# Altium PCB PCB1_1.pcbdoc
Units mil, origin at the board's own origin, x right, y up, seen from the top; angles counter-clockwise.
Board outline 3218.62 x 3136.34 mil, 4 copper layers (Top Layer, GND, VIN, Bottom Layer), stack 64.007 mil thick; 37 components, 44 nets, 178 pads, 47 vias.
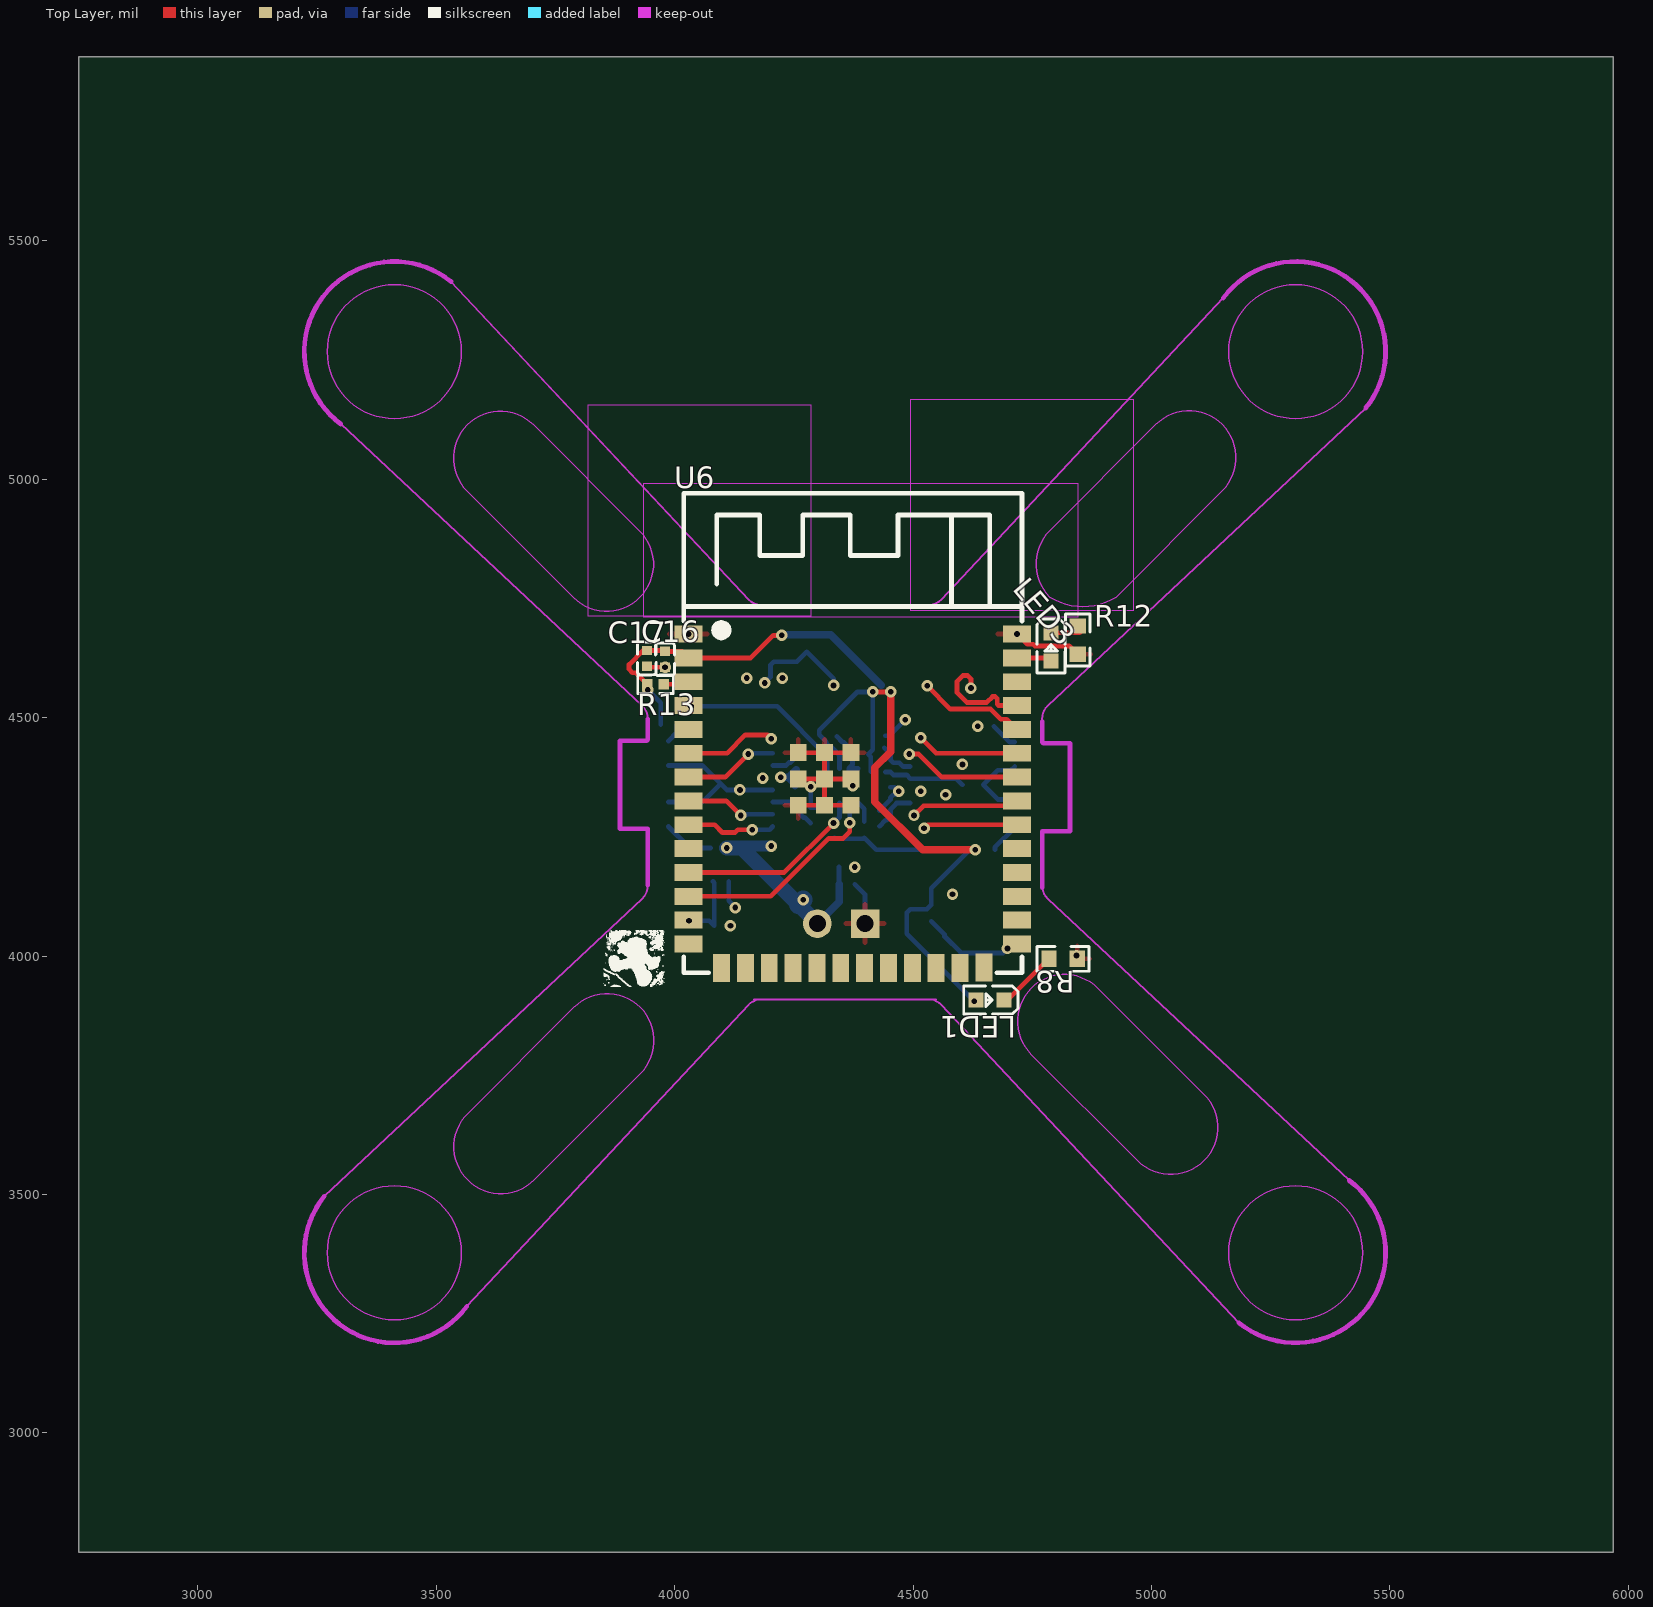
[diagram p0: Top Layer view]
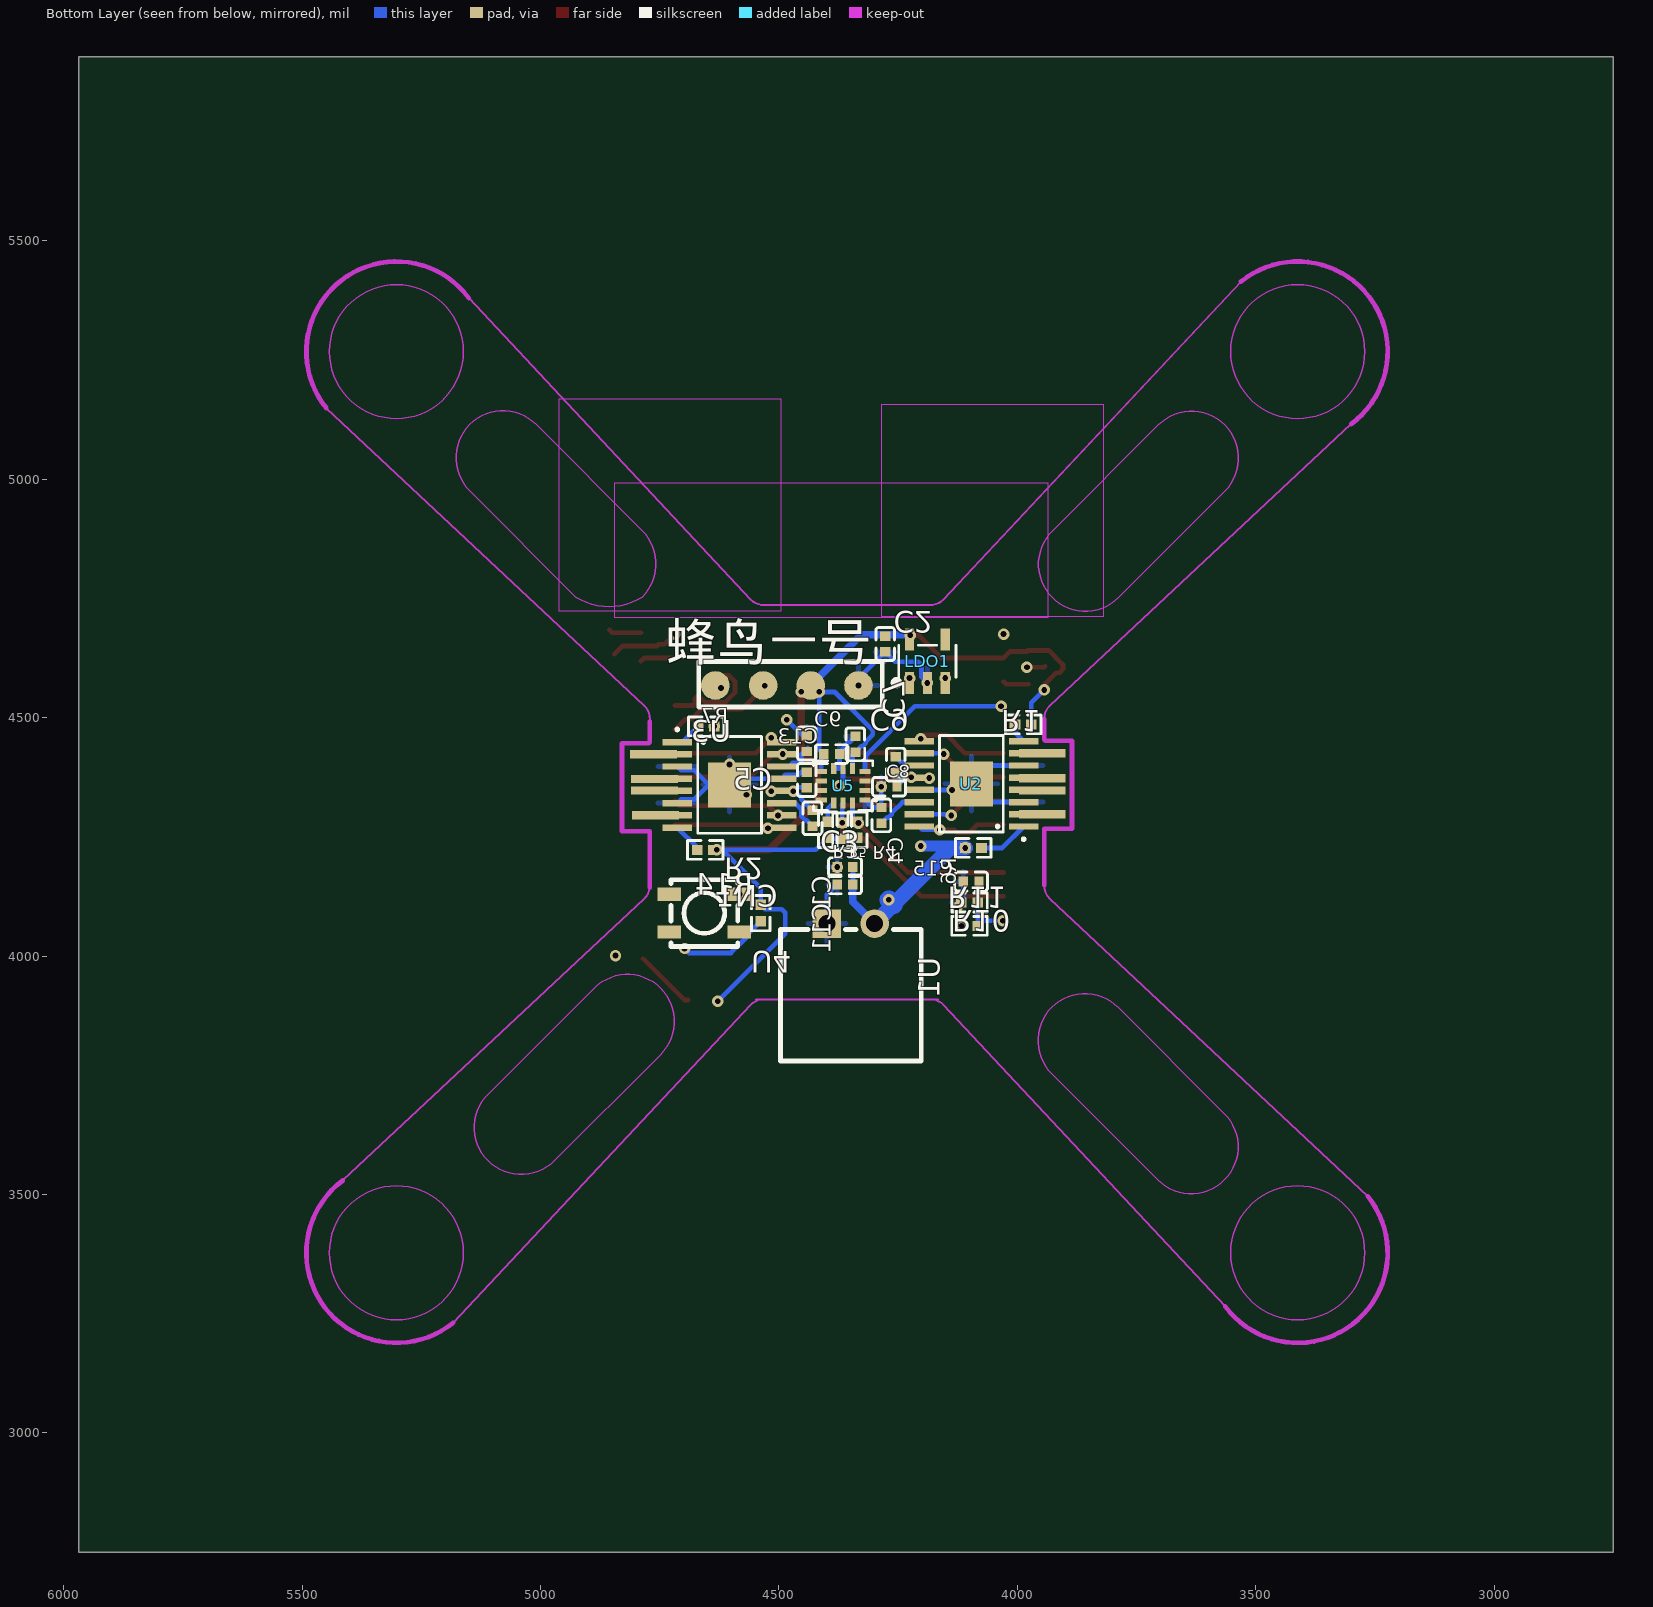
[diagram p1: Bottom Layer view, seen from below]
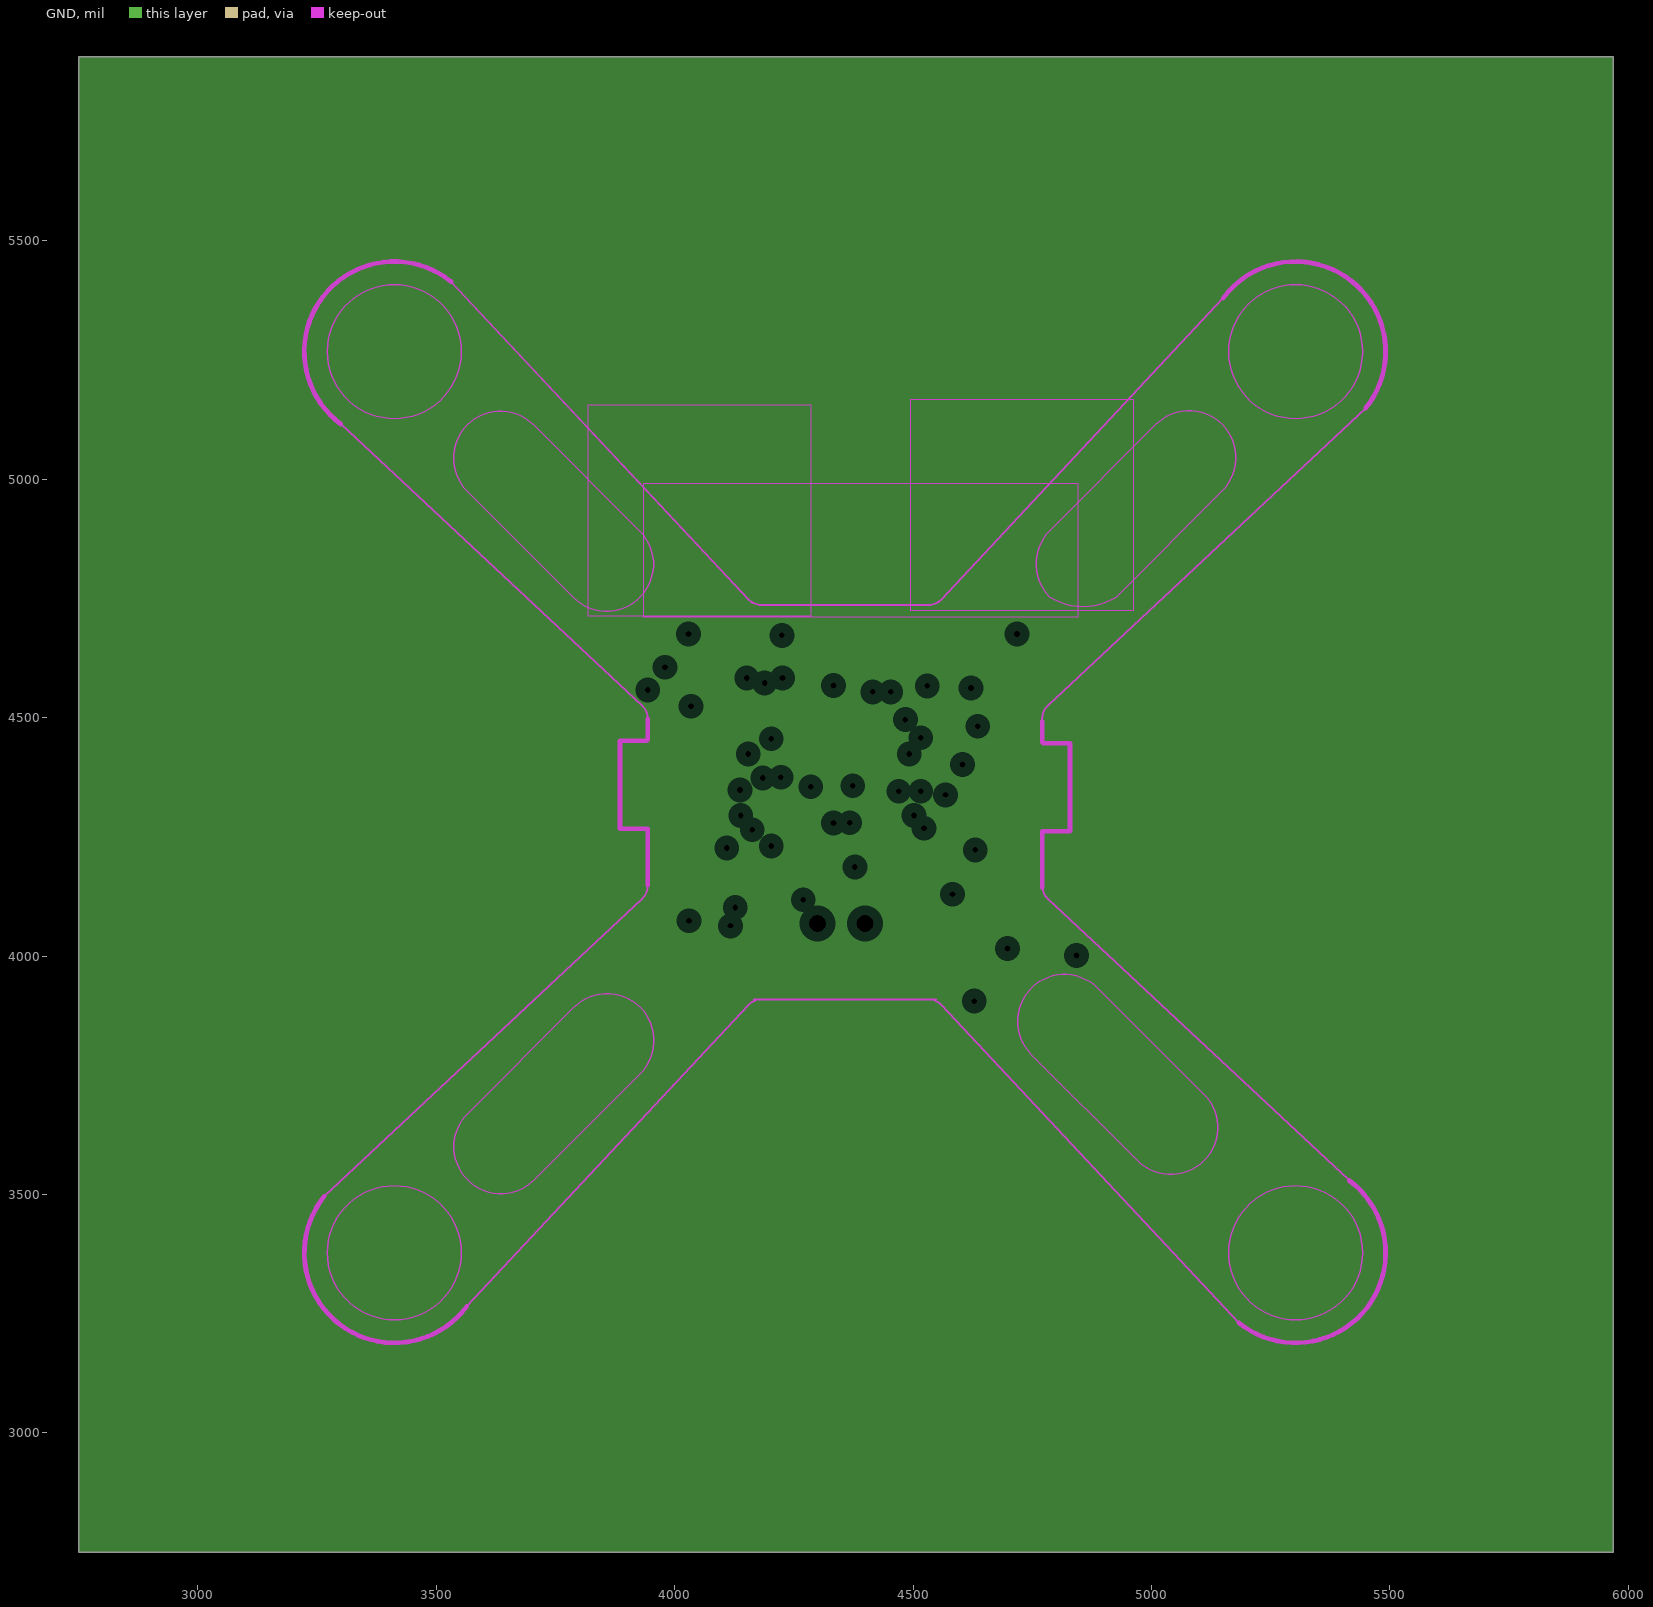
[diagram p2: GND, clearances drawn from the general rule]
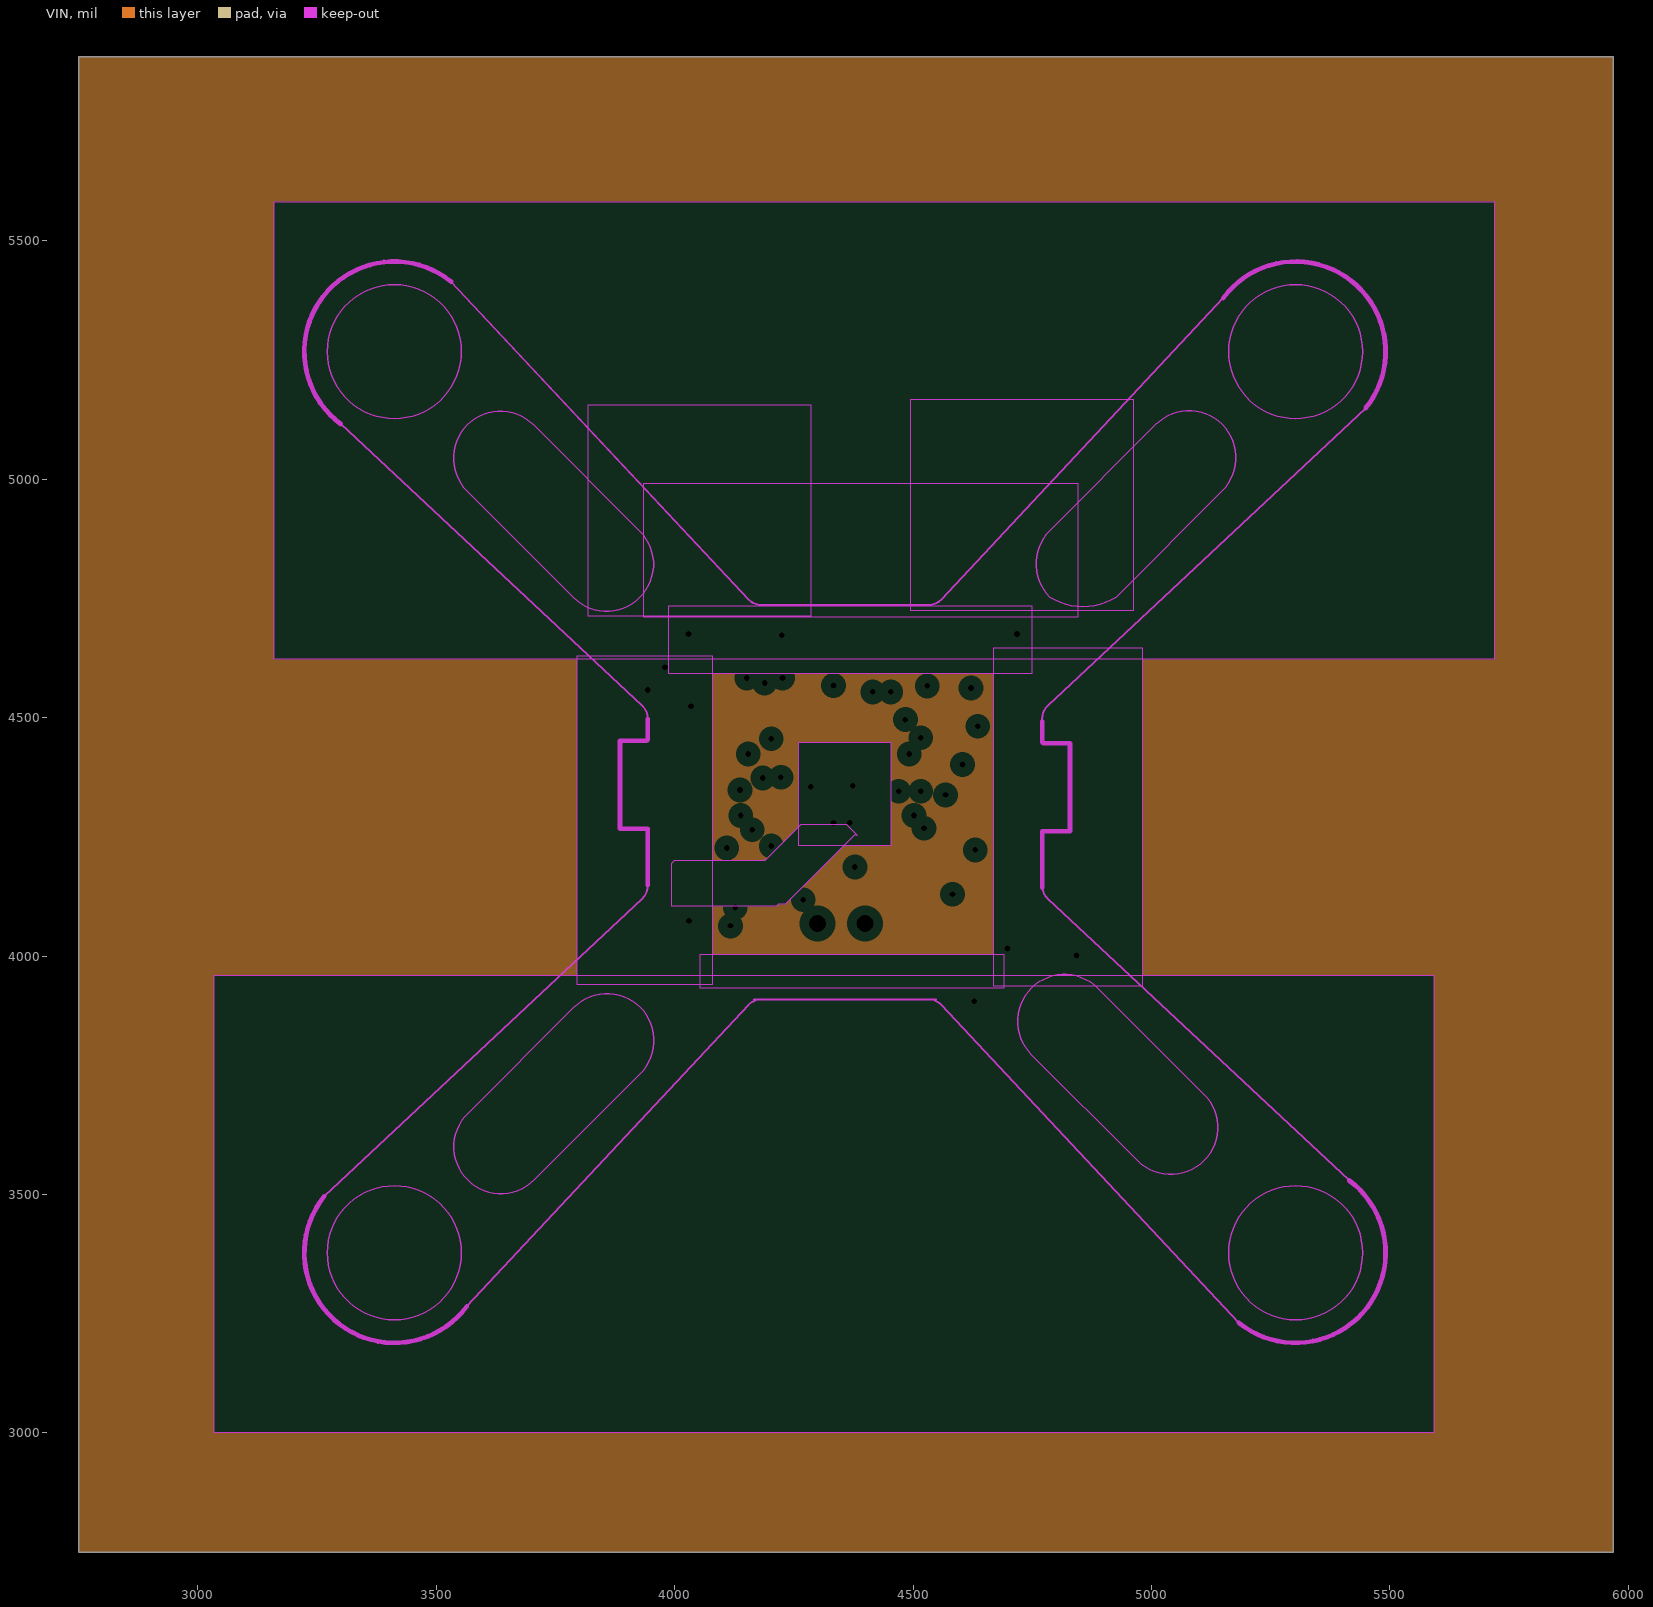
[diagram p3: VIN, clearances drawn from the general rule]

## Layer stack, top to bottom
Top Layer: signal copper 1.378
Dielectric1: surface 8.283, 7628 RC49% 8.6mil, Dk 0
GND: plane copper 1.378
Dielectric2: surface 41.929, 1.1mm H/HOZ Copper, Dk 0
VIN: plane copper 1.378
Dielectric3: surface 8.283, 7628 RC49% 8.6mil, Dk 0
Bottom Layer: signal copper 1.378

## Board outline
5968.62,2750 2750,2750 2750,5886.34 5968.62,5886.34

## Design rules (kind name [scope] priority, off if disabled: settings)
BoardOutlineClearance copperThickness1oz [All] p0: genericclearance=10 ignorepadtopadclearanceinfootprint=FALSE except(0: Arc-SplitContinuation Track-SplitContinuation SMDPad-SplitContinuation THPad-SplitContinuation Via-SplitContinuation Fill-SplitContinuation Poly-SplitContinuation Region-SplitContinuation Text-SplitContinuation)
BoardOutlineClearance copperThickness2oz [All] p0: genericclearance=10 ignorepadtopadclearanceinfootprint=FALSE except(0: Arc-SplitContinuation Track-SplitContinuation SMDPad-SplitContinuation THPad-SplitContinuation Via-SplitContinuation Fill-SplitContinuation Poly-SplitContinuation Region-SplitContinuation Text-SplitContinuation)
BoardOutlineClearance copperThicknessInner0.5oz [All] p0: genericclearance=10 ignorepadtopadclearanceinfootprint=FALSE except(0: Arc-SplitContinuation Track-SplitContinuation SMDPad-SplitContinuation THPad-SplitContinuation Via-SplitContinuation Fill-SplitContinuation Poly-SplitContinuation Region-SplitContinuation Text-SplitContinuation)
BoardOutlineClearance otherClearance [All] p0: genericclearance=10 ignorepadtopadclearanceinfootprint=FALSE except(0: Arc-SplitContinuation Track-SplitContinuation SMDPad-SplitContinuation THPad-SplitContinuation Via-SplitContinuation Fill-SplitContinuation Poly-SplitContinuation Region-SplitContinuation Text-SplitContinuation)
Clearance copperThickness1oz [All] p1: gap=7 ignorepadtopadclearanceinfootprint=FALSE
Clearance copperThickness2oz [All] p1: gap=7 ignorepadtopadclearanceinfootprint=FALSE
Clearance copperThicknessInner0.5oz [All] p1: gap=7 ignorepadtopadclearanceinfootprint=FALSE
Clearance otherClearance [All] p1: gap=7 ignorepadtopadclearanceinfootprint=FALSE
DiffPairsRouting differentialPair [All] p1: maxuncoupledlength=10 minlimit=5.9843 maxlimit=Infinity mostfreqgap=5.9843 toplayer_minwidth=5 toplayer_prefwidth=10 toplayer_maxwidth=100 bottomlayer_minwidth=5 bottomlayer_prefwidth=10 bottomlayer_maxwidth=100
PasteMaskExpansion pasteMaskExpansion [All] p1: expansion=0
PlaneConnect innerPlane [All] p1: planeconnectstyle=Relief reliefexpansion=20 reliefentries=4 reliefconductorwidth=10 reliefairgap=10
PolygonConnect copperRegion [All] p1: connectstyle=Relief reliefentries=4 reliefconductorwidth=10 polygonreliefangle="90 Angle" airgapwidth=10
RoutingVias viaSize [All] p1: viastyle="Through Hole" holewidth=12.0078 minholewidth=7.874 maxholewidth=248.0314 width=12.0078 minwidth=7.874 maxwidth=248.0314
SolderMaskExpansion solderMaskExpansion [All] p1: useseparateexpansions=TRUE expansion=2.0079 expansionbottom=2.0079
Width copperThickness1oz [All] p1: maxlimit=100 minlimit=4 preferedwidth=10
Width copperThickness2oz [All] p1: maxlimit=100 minlimit=8 preferedwidth=10
Width copperThickness0.5oz [All] p1: maxlimit=100 minlimit=4 preferedwidth=10

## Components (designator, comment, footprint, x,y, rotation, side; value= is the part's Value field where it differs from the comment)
C1 "" C0402 4361.34,4186.65 r180 bottom
C2 "" C0402 4277.01,4654.49 r270 bottom
C3 "" C0402 4429.61,4289.06 r90 bottom
C4 "" C0402 4285.04,4295.08 r90 bottom
C5 "" C0402 4441.65,4369.37 r270 bottom
C6 "" C0402 4441.65,4445.67 r90 bottom
C7 "" C0402 4254.92,4401.5 r270 bottom
C8 "" C0402 4268.98,4355.31 r0 bottom
C9 "" C0402 4339.73,4444.14 r90 bottom
C11 "" C0402 4361.34,4150.51 r180 bottom
C13 "" C0402 4389.45,4423.58 r180 bottom
C15 "" C0402 4097.02,4156.53 r180 bottom
C16 "" C0402 3979.84,4622.36 r90 top
C17 "" C0402 3941.69,4624.37 r90 top
CN1 "" CONN-TH_2P-P2.50_WAFER-XH254WZ-2A 4349.29,4068.19 r180 bottom
LDO1 "" SOT-23-5_L3.0-W1.7-P0.95-LS2.8-BL 4188.66,4618.35 r180 bottom
LED1 "" LED0603-RD 4661.15,3908.18 r180 top
LED3 "" LED0603-RD 4789.02,4648.46 r270 top
R1 "" R0402 3987.87,4485.83 r0 bottom
R2 "" R0402 4654.49,4222.8 r0 bottom
R3 "" R0402 4397.48,4264.96 r270 bottom
R4 "" R0402 4335.24,4264.96 r270 bottom
R5 "" R0402 4367.36,4262.95 r270 bottom
R6 "" R0402 4092.28,4226.81 r180 bottom
R7 "" R0402 4652.48,4481.81 r0 bottom
R8 "" R0603 4814.48,3994.36 r0 top
R10 "" R0402 4100.3,4063.44 r0 bottom
R11 "" R0402 4100.31,4112.36 r180 bottom
R12 "" R0603 4845.24,4662.52 r270 top
R13 "" R0402 3959.76,4570.16 r0 top
R14 "" R0402 4538.03,4090.28 r270 bottom
U1 "" 4p贴片 4043.15,4207.56 r90 bottom
U2 "" ETSSOP-16_L5.0-W4.4-P0.65-LS6.4-BL-EP 4096.3,4361.34 r90 bottom
U3 "" ETSSOP-16_L5.0-W4.4-P0.65-LS6.4-BL-EP 4603.54,4359.18 r270 bottom
U4 "" KEY-SMD_4P-L3.3-W3.3-P2.00-LS4.0 4656.5,4090.28 r0 bottom
U5 "" LGA-14_L3.0-W2.5-P0.50-BR 4365.35,4357.32 r180 bottom
U6 "" WIRELM-SMD_ESP32-S3-WROOM-1 4373.39,4325.2 r0 top

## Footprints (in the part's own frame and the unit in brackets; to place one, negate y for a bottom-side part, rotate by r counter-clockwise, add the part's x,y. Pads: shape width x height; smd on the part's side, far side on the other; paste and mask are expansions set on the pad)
4p贴片 [mil]
  round 60 smd: 1(360,590) 2(360,490) 3(360,390) 4(360,290)
  silkscreen extent 315,240 410,625
C0402 [mm]
  rect 0.5x0.54 smd: 1(-0.42,0) 2(0.42,0)
  silkscreen extent -0.87,-0.5 0.87,0.5
CONN-TH_2P-P2.50_WAFER-XH254WZ-2A [mil]
  rect 60x60 hole 36: 1(-50.01,0)
  round 60 hole 36: 2(49.99,0)
  silkscreen extent -148,-288 148,-13
ETSSOP-16_L5.0-W4.4-P0.65-LS6.4-BL-EP [mm]
  rect 0.343x1.56 smd: 1(-2.275,-2.78) 2(-1.625,-2.78) 3(-0.975,-2.78) 4(-0.325,-2.78) 5(0.325,-2.78) 6(0.975,-2.78) 7(1.625,-2.78) 8(2.275,-2.78) 9(2.275,2.78) 10(1.625,2.78) 11(0.975,2.78) 12(0.325,2.78) 13(-0.325,2.78) 14(-0.975,2.78) 15(-1.625,2.78) 16(-2.275,2.78)
  rect 2.4x2.3 smd: 17(0,0)
  silkscreen extent -3.02,-2.85 2.58,1.7
KEY-SMD_4P-L3.3-W3.3-P2.00-LS4.0 [mm]
  rect 1.25x0.7 smd: 1(-1.875,1) 2(1.875,1) 3(-1.875,-1) 4(1.875,-1)
  silkscreen extent -1.78,-1.78 1.78,1.78
LED0603-RD [mm]
  rect 0.8x0.8 smd: 1(-0.749,0) 2(0.749,0)
  silkscreen extent -1.49,-0.75 1.39,0.76
LGA-14_L3.0-W2.5-P0.50-BR [mm]
  rect 0.6x0.27 smd: 1(1.17,-0.75) 2(1.17,-0.25) 3(1.17,0.25) 4(1.17,0.75) 8(-1.17,0.75) 9(-1.17,0.25) 10(-1.17,-0.25) 11(-1.17,-0.75)
  rect 0.27x0.6 smd: 5(0.5,0.92) 6(0,0.92) 7(-0.5,0.92) 12(-0.5,-0.92) 13(0,-0.92) 14(0.5,-0.92)
  silkscreen extent -1.58,-1.33 1.8,1.33
R0402 [mm]
  rect 0.566x0.54 smd: 1(-0.433,0) 2(0.433,0)
  silkscreen extent -0.94,-0.5 0.94,0.5
R0603 [mil]
  rect 31.75x34.02 smd: 1(-29.66,0) 2(29.66,0)
  silkscreen extent -55,-26 55,26
SOT-23-5_L3.0-W1.7-P0.95-LS2.8-BL [mm]
  rect 0.49x1.157 smd: 1(-0.95,-1.154) 2(0,-1.154) 3(0.95,-1.154)
  rect 0.49x1.175 smd: 4(0.95,1.154) 5(-0.95,1.154)
  silkscreen extent -1.8,-1.29 1.53,0.85
WIRELM-SMD_ESP32-S3-WROOM-1 [mm]
  rect 1.5x0.9 smd: 1(-8.75,8.895) 2(-8.75,7.625) 3(-8.75,6.355) 4(-8.75,5.085) 5(-8.75,3.815) 6(-8.75,2.545) 7(-8.75,1.275) 8(-8.75,0.005) 9(-8.75,-1.265) 10(-8.75,-2.535) 11(-8.75,-3.805) 12(-8.75,-5.075) 13(-8.75,-6.345) 14(-8.75,-7.615) 27(8.75,-7.615) 28(8.75,-6.345) 29(8.75,-5.075) 30(8.75,-3.805) 31(8.75,-2.535) 32(8.75,-1.265) 33(8.75,0.005) 34(8.75,1.275) 35(8.75,2.545) 36(8.75,3.815) 37(8.75,5.085) 38(8.75,6.355) 39(8.75,7.625) 40(8.75,8.895)
  rect 0.9x1.5 smd: 15(-6.985,-8.895) 16(-5.715,-8.895) 17(-4.445,-8.895) 18(-3.175,-8.895) 19(-1.905,-8.895) 20(-0.635,-8.895) 21(0.635,-8.895) 22(1.905,-8.895) 23(3.175,-8.895) 24(4.445,-8.895) 25(5.715,-8.895) 26(6.985,-8.865)
  rect 0.9x0.9 smd: 41(-2.9,-0.225) 41(-2.9,1.175) 41(-2.9,2.575) 41(-1.5,-0.225) 41(-1.5,1.175) 41(-1.5,2.575) 41(-0.1,-0.225) 41(-0.1,1.175) 41(-0.1,2.575)
  silkscreen extent -9,-9.14 9.02,16.39

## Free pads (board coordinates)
  rect 98.43x17.72 smd far side: 1(3947.72,4297.09) 1(3947.72,4347.28) 1(3947.72,4373.39) 1(3947.72,4425.59) 1(4758.9,4295.08) 1(4760.91,4347.28) 1(4760.91,4371.38) 1(4762.91,4423.58)

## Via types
v1: diameter 24.02, hole 12.01, Top Layer to Bottom Layer, 47 vias

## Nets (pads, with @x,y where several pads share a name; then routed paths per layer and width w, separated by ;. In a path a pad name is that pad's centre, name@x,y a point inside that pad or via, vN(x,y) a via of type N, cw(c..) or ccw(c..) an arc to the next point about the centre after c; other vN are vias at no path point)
3.3V: C2.1 C9.1 C13.1 C16.2 C17.2 LDO1.5 LED1.2 R1.1 R2.1 R3.2 R4.2 R5.2 R13.1 R14.1 U1.3 U5.5 U5.8 U6.2 | length 2453.9
  Top Layer w10: R13.1 3918.63,4594.25 3911.57,4594.25 3904.5,4601.32 3904.5,4611.32 3934.09,4640.91 C17.2 3977.83,4640.91 C16.2 4015.39,4638.9 U6.2 4159.56,4625.39 4206.73,4672.56 v1(4224.8,4672.56) ; v1(4415.55,4554.09) v1(4453.05,4554.09)
  Top Layer w15.75: v1(4453.05,4554.09) 4453.05,4428.96 4419.57,4395.47 4419.57,4323.19 4519.96,4222.8 v1(4630.39,4222.8)
  Bottom Layer w10: v1(3943.7,4558.11) 3970.83,4530.98 R1.1 ; R4.2 4337.24,4245.91 R5.2 4395.47,4245.91 R3.2 4422.61,4222.8 4618.35,4222.8 4538.03,4142.48 R14.1 4529.02,4098.31 4493.86,4098.31 4486.79,4091.24 4486.79,4047.15 v1(4628.39,3905.55) ; U5.5 4345.68,4421.65 C9.1 4327.48,4439.85 4324.55,4439.85 4318.11,4446.29 4318.11,4449.21 4303.11,4464.22 4303.11,4473.78 4383.43,4554.09 v1(4415.55,4554.09) 4415.55,4433.15 C13.1 4411.42,4418.16 U5.8
  Bottom Layer w15.75: LDO1.5@4226.06,4673.81 4326.9,4673.81 U1.3
$1N94: R6.2 U2.1 | length 107
  Bottom Layer w10: U2.1 4031.81,4226.81 R6.2
$1N101: R1.2 U2.8 | length 42.4
  Bottom Layer w10: U2.8 4004.91,4468.97 R1.2
$1N113: R2.2 U3.8 | length 64
  Bottom Layer w10: R2.2 4671.53,4228.14 U3.8
$1N114: R7.2 U3.1 | length 57.2
  Bottom Layer w10: R7.2 4702.58,4448.75 U3.1
$1N160: U6.5
$1N177: U6.14
$1N180: U6.10
$1N183: U6.15
$1N185: LED3.1 R12.1 | length 68.8
  Top Layer w10: LED3.1 4849.08,4677.95 R12.1@4855.28,4684.15
$1N186: LED3.2 U6.39 | length 73.8
  Top Layer w10: U6.39 4782.61,4625.39 LED3.2
$1N211: LED1.1 R8.1 | length 129.9
  Top Layer w10: LED1.1 4698.66,3908.19 R8.1
$1N226: U6.23
AD: C15.2 R10.1 R11.2 U6.13 | length 151.9
  Bottom Layer w10: v1(4030.04,4074.21) 4072.48,4074.21 R10.1 4083.26,4112.34 4083.27,4153.74 C15.2
BOOTLADER: R14.2 U4.1 U6.27 | length 193.5
  Bottom Layer w10: R14.2 4566.14,4045.13 4566.14,4041.11 4600.52,4006.73 4688.5,4006.73 v1(4697.76,4015.98)
CSB: R3.1 U5.12 | length 44.3
  Bottom Layer w10: U5.12 4397.48,4308.67 R3.1
EN: R13.2 U6.3 | length 54.3
  Top Layer w10: R13.2 4023.66,4570.16 U6.3
GND: C1.1 C2.2 C4.2 C5.1 C6.2 C8.2 C9.2 C11.1 C13.2 C15.1 C16.1 C17.1 CN1.1 LDO1.2 R8.2 R11.1 R12.2 U1.4 U2.3 U2.6 U2.13 U2.17 U3.3 U3.6 U3.13 U3.17 U4.3 U5.1 U5.6 U5.7 U6.1 U6.40 U6.41 | length 1973.3
  Top Layer w10: C17.1 3943.7,4605.82 v1(3979.84,4605.82) ; U6.41@4259.21,4316.33 U6.41@4314.33,4316.33 ; U6.41@4259.21,4371.45 U6.41@4314.33,4371.45 ; U6.41@4259.21,4426.57 U6.41@4314.33,4426.57 ; U6.41@4369.45,4316.33 U6.41@4314.33,4316.33 ; U6.41@4369.45,4371.45 U6.41@4314.33,4371.45 ; U6.41@4369.45,4426.57 U6.41@4314.33,4426.57 ; v1(4717.88,4675.39) 4739.18,4654.09 4751.95,4654.09 4755.57,4650.47 4827.62,4650.47 R12.2 ; U6.41@4314.33,4316.33 U6.41@4314.33,4371.45 ; U6.41@4314.33,4371.45 U6.41@4314.33,4426.57
  Bottom Layer w10: U2.3 4057.91,4322.95 U2.17 ; U2.6 4057.91,4399.73 U2.17 ; C15.1 4113.56,4116.15 R11.1 ; v1(4188.66,4572.93) 4200.71,4584.97 4200.71,4610.31 4207.78,4617.39 4256.45,4617.39 C2.2 4333.15,4581.81 v1(4333.15,4567.56) ; U2.13 v1(4136.87,4348.54) 4109.1,4348.54 U2.17 ; v1(4285.52,4355.31) 4285.52,4312.1 C4.2 4303.11,4311.62 U5.1 ; C9.2 4351.98,4448.43 4354.91,4448.43 4361.34,4441.99 4361.34,4439.06 4372.91,4427.5 C13.2 4372.91,4401.09 U5.6 ; v1(4373.39,4357.33) 4365.36,4365.35 U5.6 ; C11.1 4399.29,4129.1 CN1.1 ; U5.7 U5.6 ; C5.1 4452.76,4385.91 4458.84,4379.83 4486.24,4379.83 U3.13 4590.74,4371.98 U3.17 ; C6.2 4450.16,4462.21 v1(4483.82,4495.87) ; U3.6 4705.14,4328.64 4677.74,4328.64 4647.2,4359.18 4677.74,4389.72 4705.14,4389.72 U3.3
  other v1: 4842.63,4001.13 4126.91,4101.73 4582.68,4129.65 4377.88,4186.65 4568.15,4338.15 4603.54,4401.96 4028.9,4675.39
INT1: U5.4 U6.4 | length 361.1
  Bottom Layer w10: v1(4034.06,4523.98) 4214.76,4523.98 4318.11,4420.63 4318.11,4413.21 4319.29,4412.03 U5.4
M1IN1: U3.16 U6.35 | length 215.3
  Top Layer w10: v1(4515.94,4457.72) 4548.27,4425.39 U6.35
M1IN2: U3.15 U6.34 | length 246
  Top Layer w10: v1(4491.85,4423.58) 4511.93,4423.58 4560.12,4375.39 U6.34
M1OUT1: pad.1@4762.91,4423.58 U3.2
M1OUT2: pad.1@4760.91,4371.38 U3.4
M2IN1: U2.9 U6.6 | length 193
  Top Layer w10: U6.6 4110.16,4425.39 4148.5,4463.74 4194.69,4463.74 v1(4202.72,4455.71)
M2IN2: U2.10 U6.7 | length 194.9
  Top Layer w10: U6.7 4106.34,4375.39 v1(4154.53,4423.58)
  Bottom Layer w10: v1@4156.54,4425.59 4205.48,4425.59 U2.10
M2OUT1: pad.1@3947.72,4425.59 U2.7
M2OUT2: pad.1@3947.72,4373.39 U2.5
M3IN1: U2.16 U6.9 | length 189
  Top Layer w10: U6.9 4083.86,4275.39 4100.31,4258.94 4126.42,4258.94 4132.44,4264.96 v1(4162.56,4264.96)
  Bottom Layer w10: v1(4162.56,4264.96) 4198.94,4264.96 U2.16
M3IN2: U2.15 U6.8 | length 192.4
  Top Layer w10: U6.8 4108.15,4325.39 v1(4138.46,4295.08)
  Bottom Layer w10: v1@4136.46,4295.08 4148.5,4295.08 4150.78,4297.36 U2.15
M3OUT1: pad.1@3947.72,4297.09 U2.2
M3OUT2: pad.1@3947.72,4347.28 U2.4
M4IN1: U3.9 U6.32 | length 198
  Top Layer w10: v1(4523.02,4267.93) 4530.48,4275.39 U6.32
M4IN2: U3.10 U6.33 | length 228.5
  Top Layer w10: v1(4501.89,4295.08) 4521.97,4315.16 4707.64,4315.16 U6.33
M4OUT1: pad.1@4758.9,4295.08 U3.7
M4OUT2: pad.1@4760.91,4347.28 U3.5
RXD0: U1.2 U6.36 | length 226.2
  Top Layer w10: v1(4529.49,4566.65) 4578.19,4517.95 4662.54,4517.95 4683.8,4496.69 4696.58,4496.69 U6.36
SCL: R5.1 U5.13 U6.12 | length 455.6
  Top Layer w10: U6.12 4201.69,4125.39 4323.19,4246.89 4353.31,4246.89 4367.36,4260.94 v1(4367.36,4279.7)
  Bottom Layer w10: U5.13 4367.36,4319.1 v1(4367.36,4279.7)
SDA: R4.1 U5.14 U6.11 | length 394.5
  Top Layer w10: U6.11 4229.6,4175.39 v1(4333.23,4279.02)
  Bottom Layer w10: v1(4333.23,4279.02) 4345.68,4291.47 U5.14
TXD0: U1.1 U6.37 | length 234
  Top Layer w10: v1(4621.36,4562.13) 4621.36,4581.16 4614.29,4588.23 4604.29,4588.23 4592.24,4576.18 4592.24,4552.05 4612.32,4531.97 4654.45,4531.97 4666.64,4544.16 4672.46,4544.16 4676.57,4540.04 4676.57,4527.99 4679.18,4525.39 U6.37
VCP2: C7.1 U2.11 | length 56.8
  Bottom Layer w10: U2.11 4233.69,4399.73 4239.74,4405.78 4242.67,4405.78 C7.1
VCP3: C3.1 U3.11 | length 93.5
  Bottom Layer w10: C3.1 4441.86,4284.77 4444.79,4284.77 4452.4,4292.38 4452.4,4306.5 4453.7,4307.8 4453.7,4309.13 4465.36,4320.79 U3.11
VIN: C1.2 C3.2 C5.2 C7.2 C8.1 C11.2 CN1.2 LDO1.1 LDO1.3 R6.1 R7.1 R10.2 U2.12 U3.12 | length 615.6
  Bottom Layer w10: v1(4222.75,4374.98) U2.12@4232.77,4374.98 ; C11.2 C1.2 ; C3.2 4445.67,4321.66 4445.89,4321.66 4452.4,4328.17 4452.4,4332.09 4458.84,4338.53 4462.76,4338.53 v1(4469.76,4345.53) 4461.05,4354.24 4452.29,4354.24
  Bottom Layer w11.81: U2.12@4235.25,4374.98 4252.44,4357.8 C8.1
  Bottom Layer w15.75: U2.12@4232.77,4374.98 4235.25,4374.98 4238.93,4374.98 C7.2@4254.92,4390.98 ; 4322.28,4091.18 4344.8,4113.7 C11.2
  Bottom Layer w23.62: v1(4109.32,4226.81) 4113.34,4230.83 v1(4202.72,4230.83)
  Bottom Layer w31.89: v1(4109.32,4226.81) 4140.67,4226.81 4259.3,4108.18 CN1.2
  Bottom Layer w39.37: 4259.3,4108.18 v1(4269.51,4118.39)
  other v1: 4117.04,4063.44 4515.94,4345.53 4184.65,4373.39 4635.74,4481.81 4151.26,4582.97 4226.06,4582.97
VINT2: C4.1 U2.14 | length 99.4
  Bottom Layer w10: U2.14 4240.63,4322.95 4263.43,4300.15 4263.43,4297.23 4269.86,4290.79 4272.79,4290.79 C4.1
VINT3: C6.1 U3.14 | length 78.2
  Bottom Layer w10: C6.1@4439.65,4437.16 4452.4,4424.41 4452.4,4411.86 4458.84,4405.42 4471.38,4405.42 4479.24,4397.57 U3.14
pads on no net: LDO1.4 U4.2 U4.4 U5.2 U5.3 U5.9 U5.10 U5.11 U6.16 U6.17 U6.18 U6.19 U6.20 U6.21 U6.22 U6.24 U6.25 U6.26 U6.28 U6.29 U6.30 U6.31 U6.38

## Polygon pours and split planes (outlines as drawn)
GND on Top Layer (solid, remove dead copper, pour order 0): 3160.63,5535.6 5646.38,5535.6 5646.38,3030.12 3160.63,3030.12
GND on Bottom Layer (solid, remove dead copper, pour order 4): 3096.38,5590.16 5570.08,5590.16 5570.08,3028.11 3096.38,3028.11
GND on Top Layer (solid, remove dead copper, pour order 2): 3000,5636.34 5662.44,5636.34 5662.44,3140.55 3000,3140.55
GND on Bottom Layer (solid, remove dead copper, pour order 8): 3054.21,5622.28 5552.01,5622.28 5552.01,3102.4 3054.21,3102.4
GND on Bottom Layer (solid, remove dead copper, pour order 8): 3126.5,5477.72 5692.56,5477.72 5692.56,3074.29 3126.5,3074.29

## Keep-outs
VIN:
  region: 3987.87,4734.8 4748.86,4734.8 4748.86,4592.19 3987.87,4592.19
  region: 3160.63,5582.13 5718.62,5582.13 5718.62,4622.36 3160.63,4622.36
  region: 3034.15,3959.76 5592.15,3959.76 5592.15,3000 3034.15,3000
  region: 4260.54,4448.17 4453.54,4448.17 4453.54,4230.98 4260.54,4230.98
  region: 3993.9,4104.33 3993.9,4194.69 3999.92,4200.71 4189.56,4200.71 4265.37,4276.52 4359.82,4276.52 4383.43,4252.91 4376.93,4252.91 4232.36,4108.35 4216.77,4108.35 4212.76,4104.33
  region: 4669.22,4646.13 4980.31,4646.13 4980.31,3936.7 4669.22,3936.7
  region: 4054.13,4003.94 4690.63,4003.94 4690.63,3932.71 4054.13,3932.71
  region: 3796.15,4629.94 4078.5,4629.94 4078.5,3940.06 3796.15,3940.06
Board Outline Layer:
  region: 3927.81,3892.58 cw(c3858.22,3822.98) 3927.81,3753.39 3705.1,3530.68 cw(c3635.5,3600.27) 3565.91,3530.68 cw(c3635.5,3600.27) 3565.91,3669.87 3788.62,3892.58 cw(c3858.22,3822.98)
  region: 3927.81,3892.58 cw(c3858.22,3822.98) 3927.81,3753.39 3705.1,3530.68 cw(c3635.5,3600.27) 3565.91,3530.68 cw(c3635.5,3600.27) 3565.91,3669.87 3788.62,3892.58 cw(c3858.22,3822.98)
  region: 3552.8,3377.87 cw(c3412.25,3377.87) 3271.69,3377.87 cw(c3412.25,3377.87)
  circle w0.1: c3412.25,3377.87 r140.55
  region: 3552.8,3377.87 cw(c3412.25,3377.87) 3271.69,3377.87 cw(c3412.25,3377.87)
  region: 5442.57,3377.89 cw(c5302.02,3377.89) 5161.47,3377.89 cw(c5302.02,3377.89)
  circle w0.1: c5302.02,3377.89 r140.55
  region: 5442.57,3377.89 cw(c5302.02,3377.89) 5161.47,3377.89 cw(c5302.02,3377.89)
  region: 4747.94,3932.82 cw(c4817.54,3863.23) 4887.13,3932.82 5109.84,3710.11 cw(c5040.25,3640.52) 5109.84,3570.92 cw(c5040.25,3640.52) 4970.65,3570.92 4747.94,3793.63 cw(c4817.54,3863.23)
  region: 4747.94,3932.82 cw(c4817.54,3863.23) 4887.13,3932.82 5109.84,3710.11 cw(c5040.25,3640.52) 5109.84,3570.92 cw(c5040.25,3640.52) 4970.65,3570.92 4747.94,3793.63 cw(c4817.54,3863.23)
  region: 5442.57,5267.65 cw(c5302.02,5267.65) 5161.47,5267.65 cw(c5302.02,5267.65)
  circle w0.1: c5302.02,5267.65 r140.55
  region: 5442.57,5267.65 cw(c5302.02,5267.65) 5161.47,5267.65 cw(c5302.02,5267.65)
  region: 4786.45,4752.94 cw(c4856.05,4822.54) 4786.45,4892.14 5009.16,5114.85 cw(c5078.76,5045.25) 5148.36,5114.85 cw(c5078.76,5045.25) 5148.36,4975.65 4925.65,4752.94 cw(c4856.05,4862.39)
  region: 4786.45,4752.94 cw(c4856.05,4822.54) 4786.45,4892.14 5009.16,5114.85 cw(c5078.76,5045.25) 5148.36,5114.85 cw(c5078.76,5045.25) 5148.36,4975.65 4925.65,4752.94 cw(c4856.05,4862.39)
  region: 3935.67,4991.81 4845.24,4991.81 4845.24,4710.71 3935.67,4710.71
  region: 3552.8,5267.65 cw(c3412.25,5267.65) 3271.7,5267.65 cw(c3412.25,5267.65)
  circle w0.1: c3412.25,5267.65 r140.55
  region: 3552.8,5267.65 cw(c3412.25,5267.65) 3271.7,5267.65 cw(c3412.25,5267.65)
  region: 3926.96,4752.09 cw(c3857.36,4821.68) 3787.77,4752.09 3565.06,4974.8 cw(c3634.65,5044.39) 3565.06,5113.99 cw(c3634.65,5044.39) 3704.25,5113.99 3926.96,4891.28 cw(c3857.36,4821.68)
  region: 3926.96,4752.09 cw(c3857.36,4821.68) 3787.77,4752.09 3565.06,4974.8 cw(c3634.65,5044.39) 3565.06,5113.99 cw(c3634.65,5044.39) 3704.25,5113.99 3926.96,4891.28 cw(c3857.36,4821.68)
  region: 3819.21,5156.46 4285.04,5156.46 4285.04,4712.72 3819.21,4712.72
  region: 4495.47,5167.97 4961.3,5167.97 4961.3,4724.23 4495.47,4724.23
  lines w0.1: 4887.13,3932.82 5109.84,3710.11 cw(c5040.25,3640.52) 5109.84,3570.92 cw(c5040.25,3640.52) 4970.65,3570.92 4747.94,3793.63 cw(c4817.54,3863.23) 4747.94,3932.83 cw(c4817.54,3863.23) 4887.13,3932.83 ; 3565.06,4974.8 3787.77,4752.09 ccw(c3857.36,4821.68) 3926.96,4752.09 ccw(c3857.36,4821.68) 3926.96,4891.28 3704.25,5113.99 ccw(c3634.65,5044.39) 3565.06,5113.99 ccw(c3634.65,5044.39) 3565.06,4974.8 ; 3565.91,3530.68 ccw(c3635.5,3600.27) 3705.1,3530.68 3927.81,3753.39 ccw(c3858.22,3822.98) 3927.81,3892.58 ccw(c3858.22,3822.98) 3788.62,3892.58 3565.91,3669.87 ccw(c3635.5,3600.27) 3565.91,3530.68 ; 4786.45,4752.94 cw(c4856.05,4822.54) 4786.45,4892.14 5009.16,5114.85 cw(c5078.76,5045.25) 5148.36,5114.85 cw(c5078.76,5045.25) 5148.36,4975.65 4925.65,4752.94 cw(c4856.05,4862.39) 4786.45,4752.94
  lines w3.94: 3265.28,3496.52 3932.22,4120.56 ccw(c3904.38,4148.4) 3943.75,4148.4 ; 3299.7,5115.97 3932.23,4524.97 ; 3530.9,5414.62 4154.95,4747.68 ccw(c4182.77,4775.53) 4182.77,4736.16 4531.5,4736.16 ccw(c4531.5,4775.53) 4559.34,4747.69 ; 3563.93,3265.32 4154.93,3897.85 cw(c4182.77,3870.01) 4182.77,3909.38 ; 3932.22,4524.98 cw(c3904.38,4497.14) 3943.75,4497.14 ; 4166.46,3909.38 4547.81,3909.38 ; 4531.5,3909.38 cw(c4531.5,3870.01) 4559.34,3897.85 5183.37,3230.93 ; 4559.33,4747.67 5150.33,5380.2 ; 4770.52,4148.4 ccw(c4809.89,4148.4) 4782.05,4120.56 5414.57,3529.57 ; 4770.52,4497.14 cw(c4809.89,4497.14) 4782.05,4524.98 ; 4782.04,4524.96 5448.98,5149
  lines w10: 3265.28,3496.52 ccw(c3412.25,3377.87) 3563.93,3265.32 ; 3299.7,5115.97 cw(c3412.25,5267.65) 3530.9,5414.62 ; 3943.75,4148.4 3943.75,4266.97 3935.67,4266.97 3885.47,4266.97 3885.47,4451.69 3941.69,4451.69 3943.75,4453.75 3943.75,4497.14 ; 4770.9,4143.22 4770.9,4261.78 4778.98,4261.78 4829.17,4261.78 4829.17,4446.51 4772.95,4446.51 4770.9,4448.56 4770.9,4491.95 ; 5150.33,5380.2 cw(c5302.02,5267.65) 5448.98,5149 ; 5183.37,3230.93 ccw(c5302.02,3377.89) 5414.57,3529.57

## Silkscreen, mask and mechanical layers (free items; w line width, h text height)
Top Silkscreen Layer:
  drawing of 1607 lines, arcs and shapes, not listed
Bottom Silkscreen Layer:
  text "蜂鸟一号" at 4738.82,4620.35 h78.74
Mechanical Layer:
  circle w0.1: c3412.25,3377.87 r140.55
  circle w0.1: c5302.02,3377.89 r140.55
  circle w0.1: c5302.02,5267.65 r140.55
  circle w0.1: c3412.25,5267.65 r140.55
  lines w0.1: 4887.13,3932.82 5109.84,3710.11 cw(c5040.25,3640.52) 5109.84,3570.92 cw(c5040.25,3640.52) 4970.65,3570.92 4747.94,3793.63 cw(c4817.54,3863.23) 4747.94,3932.83 cw(c4817.54,3863.23) 4887.13,3932.83 ; 3565.06,4974.8 3787.77,4752.09 ccw(c3857.36,4821.68) 3926.96,4752.09 ccw(c3857.36,4821.68) 3926.96,4891.28 3704.25,5113.99 ccw(c3634.65,5044.39) 3565.06,5113.99 ccw(c3634.65,5044.39) 3565.06,4974.8 ; 3565.91,3530.68 ccw(c3635.5,3600.27) 3705.1,3530.68 3927.81,3753.39 ccw(c3858.22,3822.98) 3927.81,3892.58 ccw(c3858.22,3822.98) 3788.62,3892.58 3565.91,3669.87 ccw(c3635.5,3600.27) 3565.91,3530.68 ; 4786.45,4752.94 cw(c4856.05,4822.54) 4786.45,4892.14 5009.16,5114.85 cw(c5078.76,5045.25) 5148.36,5114.85 cw(c5078.76,5045.25) 5148.36,4975.65 4925.65,4752.94 cw(c4856.05,4862.39) 4786.45,4752.94

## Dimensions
3412.25,5690.55 to 5302.02,5690.55 on Document Layer
3223.37,5927.97 to 5490.9,5927.97 on Document Layer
